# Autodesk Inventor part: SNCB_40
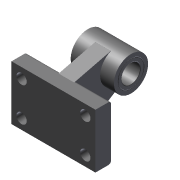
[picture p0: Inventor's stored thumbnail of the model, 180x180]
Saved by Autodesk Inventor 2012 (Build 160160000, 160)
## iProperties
Company: CAD-Verlag
Created: 2004-09
Part Number: SNCB_40
Document SubType Name: Modeling
Designer: Greiling
Manufacturer: Standard
Standards Organization: Custom
Density: 1 g/cm^3
Checked By: Jürgen Kronas
Stock Number: 10-10001
Material: Standard
Übersetzungsnorm: STEP AP203
Dateiname: s:/PartAssembly/iodir/wkb1973857_no0//0//33891_LNG_40.stp
Postprozessor: Build: 096e, Release: 9 RTM - Date: Thu 06/17/2004
Gesendete Einheiten: MILLIMETERS
Unbestimmtheit: 1.0000000000000002e-06
Author: Juergen Kronas
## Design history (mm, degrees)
feature "Basis1"
node "Volumenkörper1"
node "Volumenkörpern"
node "Oberflächenkörpern"
